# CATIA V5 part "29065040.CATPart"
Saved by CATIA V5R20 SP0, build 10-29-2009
Part number: 29065040
Definition: NONE
Nomenclature: 29065040
Source: Unknown
Description: 29065040
Bounding box of the stored display mesh (mm): x -20 to 44.548, y -46.5 to 81.048, z -36.5 to 36.5
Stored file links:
  C:\Users\Utente\Desktop\IO LAVORO\3D X SITO CF\X SITO\PLASTICA\RF1\29065040.CATPart
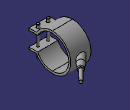
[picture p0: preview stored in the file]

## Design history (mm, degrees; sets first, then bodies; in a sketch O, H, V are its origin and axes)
Body1 "29065040" (main body)
  Solid1: solid without history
